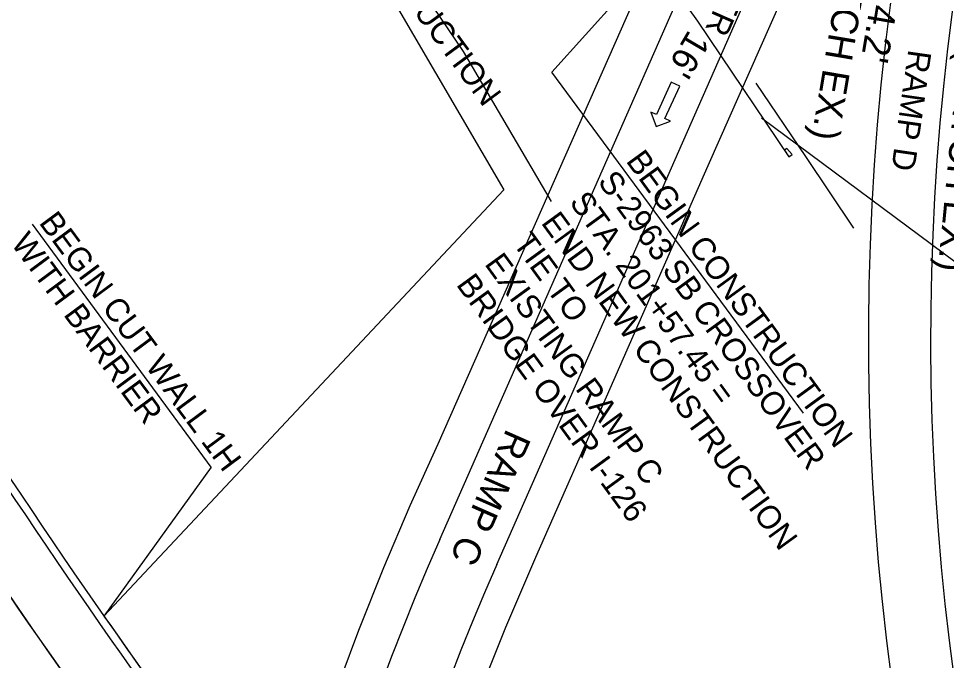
# Model space of a CAD drawing. Extents: x 1966090 to 1975830, y 788086 to 801233.
# Drawn here: x 1971355.4 to 1971594, y 795877.6 to 796042.7 of the extents above; entities that cross this region are included whole.
import ezdxf

# ---------------------------------------------------------------- set-up
doc = ezdxf.new("R2010")
doc.units = 0
for name, color, linetype in [('BR_PRESTRESSED BEAM', 7, 'Continuous'), ('BR_PROPOSED_DRAINAGE', 7, 'Continuous'), ('BR_REBAR', 7, 'Continuous'), ('RD_AR_03', 7, 'Continuous'), ('RD_EX_Driveway_txCode', 7, 'Continuous'), ('RD_EX_SU_Gas', 7, 'Continuous'), ('RD_EX_TX_Dam_ELEV', 7, 'Continuous'), ('RD_PD_PaveShd', 7, 'Continuous'), ('RD_Sketch1', 7, 'Continuous'), ('RD_Sketch6', 7, 'Continuous'), ('RD_Sketch8', 7, 'Continuous')]:
    doc.layers.add(name, color=color, linetype=linetype)

msp = doc.modelspace()

# ---------------------------------------------------------------- linework, layer by layer
at = {"layer": 'BR_PRESTRESSED BEAM'}
for p, q in [((1971517.68, 796059.3), (1971529.98, 796041.97)), ((1971529.98, 796041.97), (1971553.47, 796007.15)), ((1971552.97, 796009.23), (1971552.35, 796008.81)), ((1971552.35, 796008.81), (1971553.47, 796007.15)), ((1971554.3, 796007.71), (1971552.97, 796009.23)), ((1971553.47, 796007.15), (1971554.3, 796007.71))]:
    msp.add_line(p, q, dxfattribs=at)
msp.add_arc((1974296, 798203.94), 3890.72, 216.39766, 221.64292, dxfattribs=at)
at = {"layer": 'BR_PROPOSED_DRAINAGE'}
for p, q in [((1971321.61, 796270.35), (1971480.17, 795998.61)), ((1971480.17, 795998.61), (1971377.33, 795889.06))]:
    msp.add_line(p, q, dxfattribs=at)
msp.add_arc((1972855.69, 796921.19), 1803, 214.9213, 221.68841, dxfattribs=at)
at = {"layer": 'BR_REBAR'}
for radius in [1805, 1803]:
    msp.add_arc((1972855.69, 796921.19), radius, 211.88652, 221.68841, dxfattribs=at)
at = {"layer": 'RD_AR_03'}
for points in [[(1971480.73, 795886.18), (1971488.45, 795904.21), (1971507.51, 795947.55), (1971532.7, 796004.9), (1971562.28, 796071.76), (1971530.53, 796085.64), (1971463.21, 795933.23), (1971456.05, 795917.41), (1971449.25, 795901.44), (1971442.82, 795885.31), (1971438.26, 795873.18)], [(1971475.01, 795872.08), (1971480.73, 795886.18)]]:
    msp.add_lwpolyline(points, dxfattribs=at)
at = {"layer": 'RD_EX_Driveway_txCode'}
msp.add_lwpolyline([(1971525.43, 796025.29), (1971523.25, 796026.29), (1971519.42, 796017.96), (1971517.94, 796018.64), (1971519.33, 796014.89), (1971523.08, 796016.27), (1971521.6, 796016.95)], close=True, dxfattribs=at)
at = {"layer": 'RD_EX_SU_Gas'}
for radius, end in [(3784.72, 226.1479), (3784.72, 236.97136), (3796.72, 236.97136), (3842.72, 244.09898), (3854.72, 243.9112)]:
    msp.add_arc((1974296, 798203.94), radius, 216.39766, end, dxfattribs=at)
at = {"layer": 'RD_EX_TX_Dam_ELEV'}
msp.add_line((1971492.48, 795995.6), (1971469.8, 796034.17), dxfattribs=at)
for points in [[(1971469.8, 796034.17), (1971314.72, 796263.25)], [(1971544.97, 796026.06), (1971557.75, 796007.16), (1971570.07, 795988.79)]]:
    msp.add_lwpolyline(points, dxfattribs=at)
at = {"layer": 'RD_PD_PaveShd'}
for centre, radius, start, end in [((1972855.69, 796921.19), 1805, 211.88652, 221.68841), ((1974296, 798203.94), 3888.72, 216.39766, 221.6415)]:
    msp.add_arc(centre, radius, start, end, dxfattribs=at)
at = {"layer": 'RD_Sketch1'}
msp.add_arc((1972855.69, 796921.19), 1820, 209.01045, 218.45481, dxfattribs=at)
at = {"layer": 'RD_Sketch6'}
for p, q in [((1971492.55, 796028.86), (1971539.87, 796081.56)), ((1971557.2, 795941.17), (1971492.55, 796028.86)), ((1971546.41, 796017.16), (1971618.5, 795963.59)), ((1971404.95, 795927.37), (1971358.94, 795989.78)), ((1971404.95, 795927.37), (1971377.33, 795889.06))]:
    msp.add_line(p, q, dxfattribs=at)
at = {"layer": 'RD_Sketch8'}
for p, q in [((1971463.7, 795908.76), (1971561.57, 796130.77)), ((1971478.34, 795902.3), (1971576.21, 796124.32))]:
    msp.add_line(p, q, dxfattribs=at)
for centre, radius, start, end in [((1972855.69, 796921.19), 1820, 205.76109, 221.68841), ((1972855.69, 796921.19), 1836, 205.76109, 216.40394), ((1972226.58, 795960.7), 652.66, 167.91315, 225.41147), ((1972226.58, 795960.7), 636.66, 170.70317, 225.41147), ((1974296, 798203.94), 3772.72, 216.39766, 219.89735), ((1974296, 798203.94), 3808.72, 216.39766, 236.97136), ((1974296, 798203.94), 3830.72, 216.39766, 243.9112), ((1972046.23, 795651.96), 636.62, 156.21044, 245.71509), ((1974296, 798203.94), 3878.72, 216.39766, 241.30888), ((1972046.23, 795651.96), 620.62, 156.21044, 245.71509)]:
    msp.add_arc(centre, radius, start, end, dxfattribs=at)

# ---------------------------------------------------------------- texts
at = {"layer": 'RD_EX_Driveway_txCode'}
for s, height, rotation, p in [('SB CROSSOVER', 5.9996, 246.2119, (1971557.76, 796098.66)), ('(MATCH EX.)', 7, 260.4217, (1971568.78, 796068.41)), ("11.3' (MATCH EX.)", 7, 264.5357, (1971599.36, 796057.41)), ("4.2' ", 7, 260.4217, (1971574.4, 796046.54)), ("16'", 6.667, 239.4929, (1971527.77, 796040)), ('RAMP D', 6, 261.821, (1971584.23, 796034.86)), ('RAMP C', 7, 246.2119, (1971480.93, 795937.45))]:
    msp.add_text(s, height=height, rotation=rotation, dxfattribs=at).set_placement(p)
at = {"layer": 'RD_Sketch6'}
for s, height, rotation, p in [('RECONSTRUCTION ', 5.9996, 306.3537, (1971430.13, 796080.68)), ('BEGIN CONSTRUCTION', 5.9996, 306.0658, (1971511.41, 796006.04)), ('S-2963 SB CROSSOVER', 5.9996, 306.0658, (1971504.14, 796000.74)), ('STA. 201+57.45 =', 5.9996, 306.0658, (1971496.86, 795995.44)), ('BEGIN CUT WALL 1H', 5.9996, 306.5574, (1971360.45, 795990.17)), ('END NEW CONSTRUCTION', 5.9996, 306.0658, (1971489.59, 795990.15)), ('WITH BARRIER', 5.9996, 306.5574, (1971353.23, 795984.8)), ('TIE TO ', 6, 306.0658, (1971482.32, 795984.85)), ('EXISTING RAMP C', 5.9996, 306.0658, (1971475.04, 795979.55)), ('BRIDGE OVER I-126', 5.9996, 306.0658, (1971467.77, 795974.25))]:
    msp.add_text(s, height=height, rotation=rotation, dxfattribs=at).set_placement(p)

doc.saveas('drawing.dxf')
